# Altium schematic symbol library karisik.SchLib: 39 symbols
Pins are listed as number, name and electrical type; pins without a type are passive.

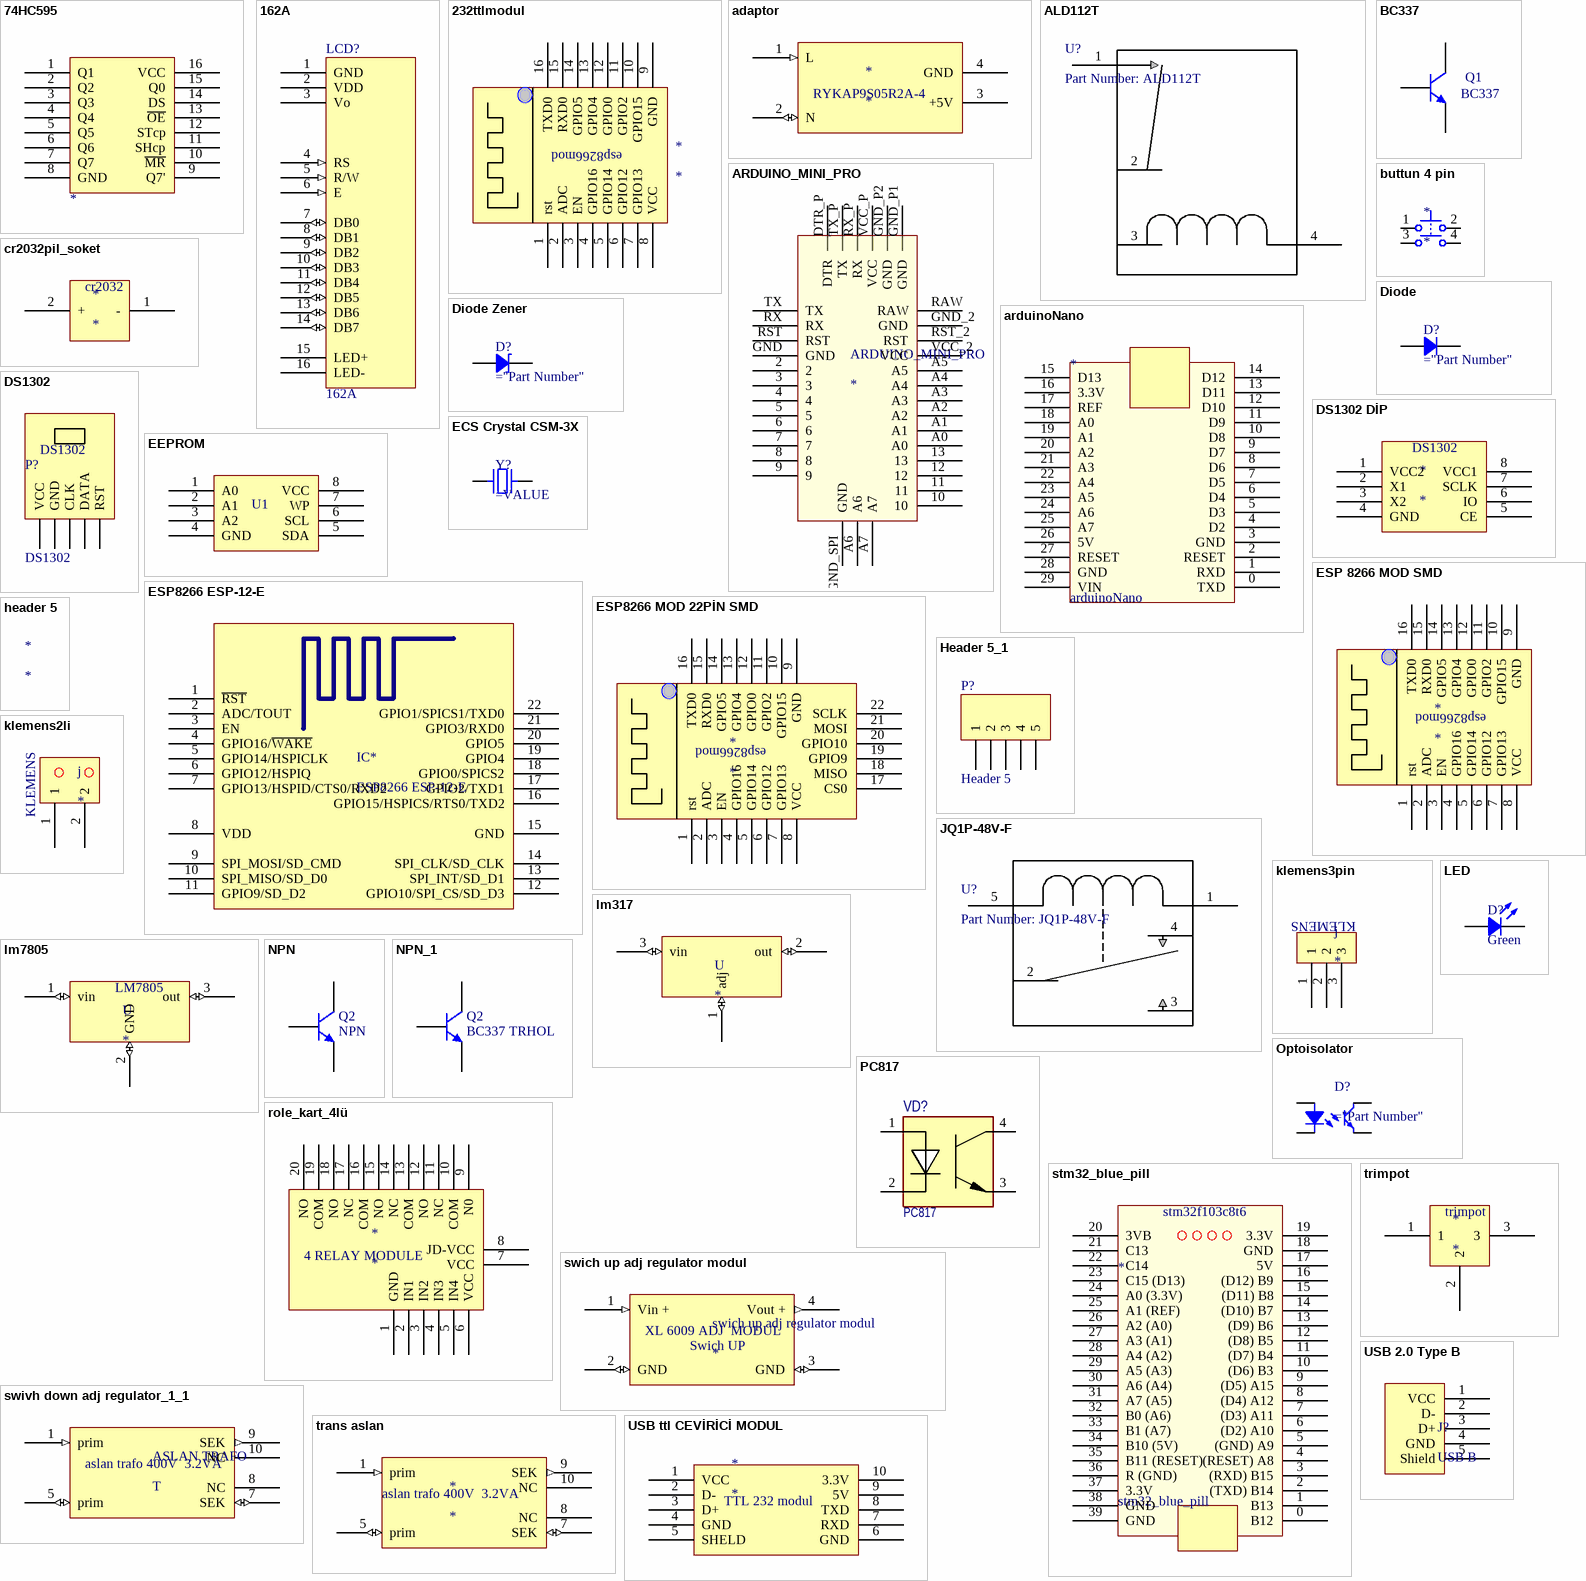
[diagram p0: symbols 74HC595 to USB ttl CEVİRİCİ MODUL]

## 74HC595
designator ?
pins: 1 Q1, 2 Q2, 3 Q3, 4 Q4, 5 Q5, 6 Q6, 7 Q7, 8 GND, 9 Q7', 10 ~{MR}, 11 SHcp, 12 STcp, 13 ~{OE}, 14 DS, 15 Q0, 16 VCC

## 162A
designator LCD?
16 char * 2 line LCD character display with b/light
footprint 162A
3D model 162a (PCB3D Model)
pins: 1 GND (power) "VSS - 0V", 2 VDD (power) "VDD - 5V", 3 Vo (hiz) "Input Voltage For LCD", 4 RS (in) "H = Data Signal, L = Instrunction Signal", 5 R/W (in) "H = Read Mode, L = Write Mode", 6 E (in) "Chip Enable (H, H->L)", 7 DB0 (io) "Chip Enable (H, H->L)", 8 DB1 (io) "Chip Enable (H, H->L)", 9 DB2 (io) "Chip Enable (H, H->L)", 10 DB3 (io) "Chip Enable (H, H->L)", 11 DB4 (io) "Chip Enable (H, H->L)", 12 DB5 (io) "Chip Enable (H, H->L)", 13 DB6 (io) "Chip Enable (H, H->L)", 14 DB7 (io) "Chip Enable (H, H->L)", 15 LED+ (power) "LED Backlight +", 16 LED- (power) "LED Backlight -"

## 232ttlmodul
designator *
pins: 1 rst, 2 ADC, 3 EN, 4 GPIO16, 5 GPIO14, 6 GPIO12, 7 GPIO13, 8 VCC, 9 GND, 10 GPIO15, 11 GPIO2, 12 GPIO0, 13 GPIO4, 14 GPIO5, 15 RXD0, 16 TXD0

## adaptor
designator *
footprint ADAPTOR
pins: 1 L (in), 2 N (io), 3 +5V, 4 GND

## ALD112T
designator U?, comment Part Number: ALD112T
No Description Available; Vendor: Panasonic; Built_By: EMA_UL_Team
footprint PAN_ALD
pins: 1, 2, 3, 4

## ARDUINO_MINI_PRO
designator ARDUINO_MINI_PRO
pins: 2, 3, 4, 5, 6, 7, 8, 9, 10, 11, 12, 13, A0, A1, A2, A3, A4, A5, A6, A7, DTR_P DTR, GND, GND_2 GND, GND_P1 GND, GND_P2 GND, GND_SPI GND, RAW, RST, RST_2 RST, RX, RX_P RX, TX, TX_P TX, VCC_2 VCC, VCC_P VCC

## arduinoNano
designator *
footprint Arduino nano (arduino nano)
pins: 0 TXD, 1 RXD, 2 RESET, 3 GND, 4 D2, 5 D3, 6 D4, 7 D5, 8 D6, 9 D7, 10 D8, 11 D9, 12 D10, 13 D11, 14 D12, 15 D13, 16 3.3V, 17 REF, 18 A0, 19 A1, 20 A2, 21 A3, 22 A4, 23 A5, 24 A6, 25 A7, 26 5V, 27 RESET, 28 GND, 29 VIN

## BC337
designator Q1
NPN TRUEHOL
footprint bc337
pins: 1 C, 2 B, 3 E

## buttun 4 pin
designator *
pins: 1, 2, 3, 4

## cr2032pil_soket
designator *
pins: 1 -, 2 +

## Diode
designator D?
Rectifier Diode
pins: 1, 2

## Diode Zener
designator D?
Zener Diode
pins: 1, 2

## DS1302
designator P?
DS1302, 5-Pin
footprint DS1302_MODULE (DS1302)
pins: 1 VCC, 2 GND, 3 CLK, 4 DATA, 5 RST

## DS1302 DİP
designator *
pins: 1 VCC2, 2 X1, 3 X2, 4 GND, 5 CE, 6 IO, 7 SCLK, 8 VCC1

## ECS Crystal CSM-3X
designator Y?
SMT Crystal
pins: 1, 2

## EEPROM
designator U1  (value not drawn)
EEPROM
footprint SOIC-8
pins: 1 A0, 2 A1, 3 A2, 4 GND, 5 SDA, 6 SCL, 7 WP, 8 VCC

## ESP8266 ESP-12-E
designator IC*
footprint ESP8266 ESP-12-E
pins: 1 ~{RST} "Reset", 2 ADC/TOUT "ADC Input Or TOUT Output", 3 EN "Chip enable", 4 GPIO16/~{WAKE} "GPIO16 or Deep-Sleep Wakeup", 5 GPIO14/HSPICLK "GPIO14 or SPI CLK", 6 GPIO12/HSPIQ "GPIO12 or SPIQ", 7 GPIO13/HSPID/CTS0/RXD2 "GPIO13 or SPID", 8 VDD "Power supply", 9 SPI_MOSI/SD_CMD "GPIO14 or SPI CLK", 10 SPI_MISO/SD_D0 "GPIO12 or SPIQ", 11 GPIO9/SD_D2 "GPIO13 or SPID", 12 GPIO10/SPI_CS/SD_D3 "GPIO15 or SPICS", 13 SPI_INT/SD_D1 "GPIO2 or TX", 14 SPI_CLK/SD_CLK "GPIO0 or SPICS2", 15 GND "Power ground", 16 GPIO15/HSPICS/RTS0/TXD2 "GPIO15 or SPICS", 17 GPIO2/TXD1 "GPIO2 or TX", 18 GPIO0/SPICS2 "GPIO0 or SPICS2", 19 GPIO4 "GPIO5", 20 GPIO5 "GPIO4", 21 GPIO3/RXD0 "GPIO3 or UART RXD", 22 GPIO1/SPICS1/TXD0 "GPIO1 or UART TXD"

## ESP8266 MOD 22PİN SMD
designator *
pins: 1 rst, 2 ADC, 3 EN, 4 GPIO16, 5 GPIO14, 6 GPIO12, 7 GPIO13, 8 VCC, 9 GND, 10 GPIO15, 11 GPIO2, 12 GPIO0, 13 GPIO4, 14 GPIO5, 15 RXD0, 16 TXD0, 17 CS0, 18 MISO, 19 GPIO9, 20 GPIO10, 21 MOSI, 22 SCLK

## ESP 8266 MOD SMD
designator *
pins: 1 rst, 2 ADC, 3 EN, 4 GPIO16, 5 GPIO14, 6 GPIO12, 7 GPIO13, 8 VCC, 9 GND, 10 GPIO15, 11 GPIO2, 12 GPIO0, 13 GPIO4, 14 GPIO5, 15 RXD0, 16 TXD0

## header 5
designator *

## Header 5_1
designator P?, comment Header 5
Header, 5-Pin
footprint HDR1X5 (Connector; Header; 5 Position)
signal-integrity model Connector
pins: 1, 2, 3, 4, 5

## JQ1P-48V-F
designator U?, comment Part Number: JQ1P-48V-F
No Description Available; Vendor: Panasonic; Built_By: EMA_UL_Team
footprint RELAY_JQ1
pins: 1 5, 2, 3, 4, 5 1

## klemens2li
designator j
footprint klemens2li (Footprint not found)
footprint PCBComponent_1
pins: 1 (oc), 2 (oc)

## klemens3pin
designator j
footprint klemens2li (Footprint not found)
footprint PCBComponent_1
pins: 1 (oc), 2 (oc), 3

## LED
designator D?, comment Green
Chip LED
pins: 1, 2

## lm317
designator U
footprint PCBComponent_1
pins: 1 adj (io), 2 out (io), 3 vin (io)

## lm7805
designator U
footprint PCBComponent_1
pins: 1 vin (io), 2 GND (io), 3 out (io)

## NPN
designator Q2
NPN Bipolar Transistor
simulation model QNPN (NPN)
signal-integrity model NPN
footprint SOT-23 (SOT23, 3-Leads, Body 3,1x2,5mm (max), Pitch 0,95mm, IPC Medium Density)
pins: 1 B, 2 E, 3 C

## NPN_1
designator Q2, comment BC337 TRHOL
NPN Bipolar Transistor
simulation model QNPN (NPN)
signal-integrity model NPN
footprint SOT-23 (SOT23, 3-Leads, Body 3,1x2,5mm (max), Pitch 0,95mm, IPC Medium Density)
pins: 1 B, 2 E, 3 C

## Optoisolator
designator D?
pins: 1, 2, 3, 4

## PC817
designator VD?  ManufacturerPartNumber: PC817  (hidden comment: *)
pins: 1, 2, 3, 4

## role_kart_4lü
designator *
pins: 1 GND, 2 IN1, 3 IN2, 4 IN3, 5 IN4, 6 VCC, 7 VCC, 8 JD-VCC, 9 N0, 10 COM, 11 NC, 12 NO, 13 COM, 14 NC, 15 NO, 16 COM, 17 NC, 18 NO, 19 COM, 20 NO

## stm32_blue_pill
designator *
footprint Arduino nano (arduino nano)
pins: 0 B12, 1 B13, 2 (TXD) B14, 3 (RXD) B15, 4 (RESET) A8, 5 (GND) A9, 6 (D2) A10, 7 (D3) A11, 8 (D4) A12, 9 (D5) A15, 10 (D6) B3, 11 (D7) B4, 12 (D8) B5, 13 (D9) B6, 14 (D10) B7, 15 (D11) B8, 16 (D12) B9, 17 5V, 18 GND, 19 3.3V, 20 3VB, 21 C13, 22 C14, 23 C15 (D13), 24 A0 (3.3V), 25 A1 (REF), 26 A2 (A0), 27 A3 (A1), 28 A4 (A2), 29 A5 (A3), 30 A6 (A4), 31 A7 (A5), 32 B0 (A6), 33 B1 (A7), 34 B10 (5V), 35 B11 (RESET), 36 R (GND), 37 3.3V, 38 GND, 39 GND

## swich up adj regulator modul
designator swich up adj regulator modul
footprint PCBComponent_1 - duplicate1
pins: 1 Vin + (in), 2 GND (io), 3 GND (io), 4 Vout + (out)

## swivh down adj regulator_1_1
designator ASLAN TRAFO, comment T
footprint Model Name (Footprint not found)
pins: 1 prim (in), 5 prim (io), 7 SEK (io), 8 NC, 9 SEK (out), 10 NC

## trans aslan
designator *
footprint aslan
footprint aslan
pins: 1 prim (in), 5 prim (io), 7 SEK (io), 8 NC, 9 SEK (out), 10 NC

## trimpot
designator *
pins: 1, 2, 3
1 alternate drawing of the same symbol

## USB 2.0 Type B
designator J?, comment USB B
pins: 1 VCC, 2 D-, 3 D+, 4 GND, 5 Shield

## USB ttl CEVİRİCİ MODUL
designator *
pins: 1 VCC, 2 D-, 3 D+, 4 GND, 5 SHELD, 6 GND, 7 RXD, 8 TXD, 9 5V, 10 3.3V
